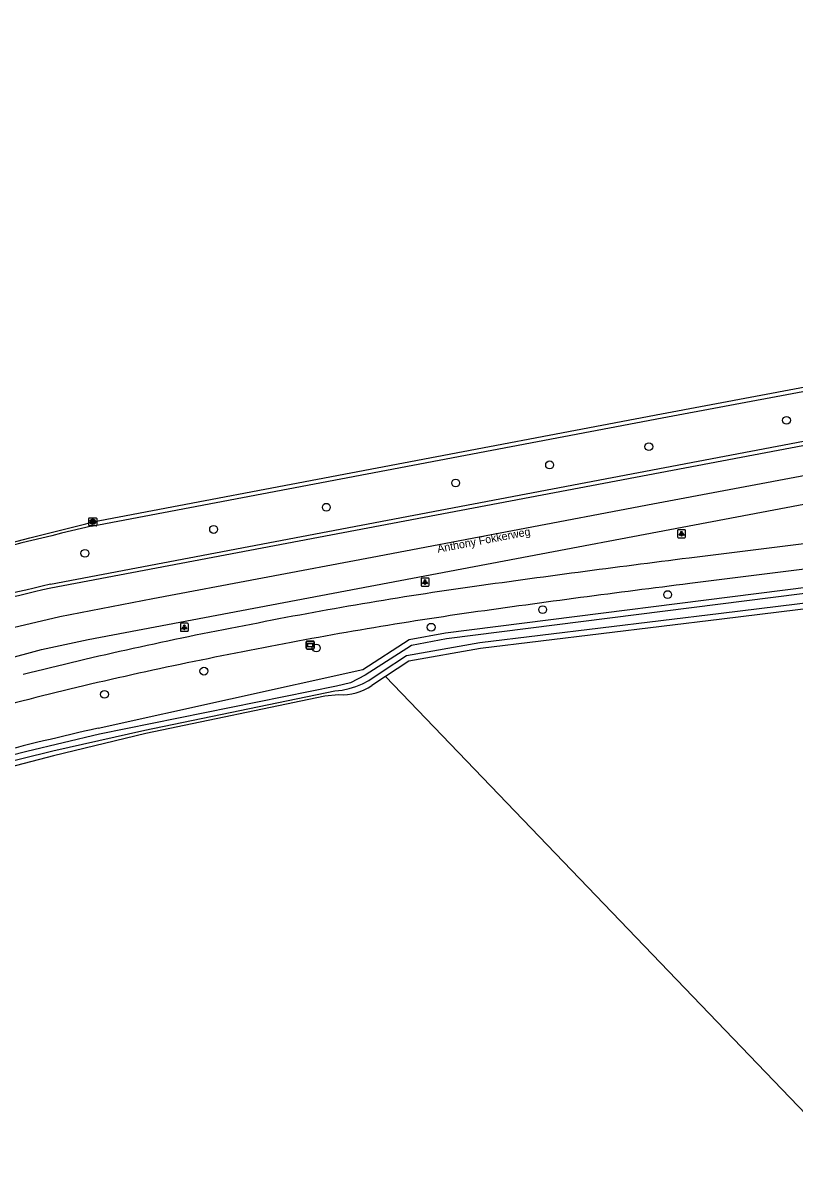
# Model space of a CAD drawing. Extents: x 157154 to 159278, y 385000 to 386650.
# Drawn here: x 157669 to 157765.4, y 386325.8 to 386470 of the extents above; entities that cross this region are included whole.
import ezdxf

# ---------------------------------------------------------------- set-up
doc = ezdxf.new("R2010")
doc.units = 0
for name, color, linetype in [('IMGEO_Berm_open', 7, 'Continuous'), ('IMGEO_Boom', 7, 'Continuous'), ('IMGEO_Bouwland', 7, 'Continuous'), ('IMGEO_Fietspad_open', 7, 'Continuous'), ('IMGEO_Groenvoorziening', 7, 'Continuous'), ('IMGEO_Kolk', 7, 'Continuous'), ('IMGEO_Lichtpunt', 7, 'Continuous'), ('IMGEO_Loofbos', 7, 'Continuous'), ('IMGEO_Openbare_ruimte_label', 7, 'Continuous'), ('IMGEO_Rijbaan_regionaal_gesloten', 7, 'Continuous'), ('IMGEO_Verklikker', 7, 'Continuous'), ('IMGEO_Waterloop', 7, 'Continuous')]:
    doc.layers.add(name, color=color, linetype=linetype)

msp = doc.modelspace()

# ---------------------------------------------------------------- linework, layer by layer
at = {"layer": 'IMGEO_Berm_open'}
for points in [[(157677.57, 386407.16), (157748.87, 386420.72), (157813.78, 386432.88)], [(157825.85, 386429.16), (157816.05, 386427.15), (157672.45, 386399.91)]]:
    msp.add_lwpolyline(points, dxfattribs=at)
for centre, radius, start, end in [((157790.4, 385918.61), 501.41, 103.0044, 107.6634), ((157771.77, 385969.6), 441.63, 102.9972, 107.3297)]:
    msp.add_arc(centre, radius, start, end, dxfattribs=at)
at = {"layer": 'IMGEO_Boom'}
for centre in [(157764.38, 386420.4), (157747.19, 386417.1), (157734.79, 386414.83), (157723.06, 386412.57), (157706.91, 386409.54), (157692.83, 386406.77), (157676.76, 386403.79), (157749.53, 386398.63), (157733.92, 386396.75), (157720, 386394.55), (157705.65, 386391.96), (157691.62, 386389.07), (157679.2, 386386.17)]:
    msp.add_circle(centre, 0.489, dxfattribs=at)
at = {"layer": 'IMGEO_Bouwland'}
for points in [[(157714.3, 386388.38), (157712.61, 386387.26)], [(157708.44, 386386.13), (157706.71, 386385.94), (157684.36, 386381.3), (157672.84, 386378.51), (157661.47, 386375.55)]]:
    msp.add_lwpolyline(points, dxfattribs=at)
msp.add_arc((157708.88, 386392.77), 6.65, 266.2635, 304.121, dxfattribs=at)
at = {"layer": 'IMGEO_Fietspad_open'}
for points in [[(157892.32, 386418.11), (157877, 386416.04), (157846.47, 386412.19), (157831.97, 386409.98), (157787.26, 386404.39), (157752.3, 386400)], [(157833.7, 386413.41), (157786.88, 386407.53), (157752.22, 386403.2)]]:
    msp.add_lwpolyline(points, dxfattribs=at)
for centre, radius, start, end in [((157993.4, 384480.42), 1937.84, 97.14941, 97.97507), ((157794.41, 385908.3), 496.16, 98.0956, 101.363), ((157954.91, 384768.71), 1643.83, 97.07995, 98.04006), ((157794.39, 385908.46), 492.83, 98.0942, 101.358), ((157786.26, 385923.76), 479.43, 100.7721, 104.1519), ((157781.31, 385945.65), 453.82, 100.6636, 104.2298), ((157811.65, 385852.76), 551.36, 104.9133, 107.8447)]:
    msp.add_arc(centre, radius, start, end, dxfattribs=at)
at = {"layer": 'IMGEO_Groenvoorziening'}
msp.add_lwpolyline([(157678.41, 386381.94), (157711.46, 386389.29), (157717.26, 386393.02), (157721.8, 386393.84), (157916.46, 386418.5)], dxfattribs=at)
msp.add_arc((157787.04, 385903.02), 491.09, 102.7805, 106.0498, dxfattribs=at)
at = {"layer": 'IMGEO_Kolk'}
for p, q in [((157677.23, 386407.29), (157677.23, 386408.14)), ((157677.31, 386408.22), (157678.16, 386408.22)), ((157677.72, 386408), (157677.75, 386408)), ((157678.24, 386408.14), (157678.24, 386407.29)), ((157678.16, 386407.22), (157677.31, 386407.22)), ((157677.74, 386407.44), (157677.72, 386407.44))]:
    msp.add_line(p, q, dxfattribs=at)
for points in [[(157677.23, 386407.29), (157677.23, 386408.14)], [(157677.31, 386408.22), (157678.16, 386408.22)], [(157678.24, 386408.14), (157678.24, 386407.29)], [(157678.16, 386407.22), (157677.31, 386407.22)], [(157677.55, 386407.92), (157677.68, 386407.92), (157677.68, 386407.77), (157677.81, 386407.92), (157677.97, 386407.92), (157677.83, 386407.77), (157677.98, 386407.52), (157677.83, 386407.52), (157677.74, 386407.68), (157677.68, 386407.61), (157677.68, 386407.52), (157677.55, 386407.52), (157677.55, 386407.92)]]:
    msp.add_lwpolyline(points, dxfattribs=at)
for centre, start, end in [((157677.31, 386408.14), 91.552, 178.448), ((157677.31, 386408.14), 91.552, 178.448), ((157678.16, 386408.14), 1.552, 88.448), ((157678.16, 386408.14), 1.552, 88.448), ((157677.31, 386407.29), 181.552, 268.448), ((157677.31, 386407.29), 181.552, 268.448), ((157678.16, 386407.29), 271.552, 358.448), ((157678.16, 386407.29), 271.552, 358.448)]:
    msp.add_arc(centre, 0.0765, start, end, dxfattribs=at)
for centre, major_axis, ratio, start_param, end_param in [((157677.72, 386407.72), (-0.387, 0.002), 0.722429, 4.712389, 7.853982), ((157677.75, 386407.72), (-0.39, 0.002), 0.717154, 1.570796, 4.712389)]:
    msp.add_ellipse(centre, major_axis=major_axis, ratio=ratio, start_param=start_param, end_param=end_param, dxfattribs=at)
at = {"layer": 'IMGEO_Lichtpunt'}
for p, q in [((157750.77, 386406.64), (157750.77, 386405.83)), ((157750.77, 386406.64), (157750.77, 386405.83)), ((157751.67, 386406.73), (157750.86, 386406.73)), ((157751.67, 386406.73), (157750.86, 386406.73)), ((157751.77, 386405.83), (157751.77, 386406.64)), ((157751.77, 386405.83), (157751.77, 386406.64)), ((157750.86, 386405.73), (157751.67, 386405.73)), ((157750.86, 386405.73), (157751.67, 386405.73)), ((157718.74, 386400.6), (157718.74, 386399.79)), ((157718.74, 386400.6), (157718.74, 386399.79)), ((157719.65, 386400.69), (157718.84, 386400.69)), ((157719.65, 386400.69), (157718.84, 386400.69)), ((157718.84, 386399.7), (157719.65, 386399.7)), ((157718.84, 386399.7), (157719.65, 386399.7)), ((157719.74, 386399.79), (157719.74, 386400.6)), ((157719.74, 386399.79), (157719.74, 386400.6)), ((157689.58, 386395.05), (157688.78, 386395.05)), ((157689.58, 386395.05), (157688.78, 386395.05)), ((157688.68, 386394.96), (157688.68, 386394.15)), ((157688.68, 386394.96), (157688.68, 386394.15)), ((157688.78, 386394.05), (157689.58, 386394.05)), ((157688.78, 386394.05), (157689.58, 386394.05)), ((157689.68, 386394.15), (157689.68, 386394.96)), ((157689.68, 386394.15), (157689.68, 386394.96))]:
    msp.add_line(p, q, dxfattribs=at)
for points in [[(157751.14, 386406.3), (157751.18, 386406.27), (157751, 386406.01), (157750.96, 386406.04), (157751.14, 386406.3)], [(157751.25, 386406.25), (157751.29, 386406.25), (157751.29, 386405.93), (157751.25, 386405.93), (157751.25, 386406.25)], [(157751.36, 386406.27), (157751.39, 386406.3), (157751.58, 386406.04), (157751.54, 386406.01), (157751.36, 386406.27)], [(157719.12, 386400.26), (157719.16, 386400.23), (157718.97, 386399.97), (157718.93, 386400), (157719.12, 386400.26)], [(157719.22, 386400.21), (157719.27, 386400.21), (157719.27, 386399.89), (157719.22, 386399.89), (157719.22, 386400.21)], [(157719.33, 386400.23), (157719.37, 386400.26), (157719.55, 386400), (157719.52, 386399.97), (157719.33, 386400.23)], [(157689.06, 386394.62), (157689.1, 386394.59), (157688.91, 386394.33), (157688.87, 386394.36), (157689.06, 386394.62)], [(157689.16, 386394.57), (157689.21, 386394.57), (157689.21, 386394.25), (157689.16, 386394.25), (157689.16, 386394.57)], [(157689.27, 386394.59), (157689.31, 386394.62), (157689.49, 386394.36), (157689.46, 386394.33), (157689.27, 386394.59)]]:
    msp.add_lwpolyline(points, dxfattribs=at)
for centre in [(157751.27, 386406.43), (157719.24, 386400.4), (157689.18, 386394.75)]:
    msp.add_circle(centre, 0.0994, dxfattribs=at)
for centre, start, end in [((157750.86, 386406.64), 90, 180), ((157750.86, 386406.64), 90, 180), ((157751.67, 386406.64), 0, 90), ((157751.67, 386406.64), 0, 90), ((157750.86, 386405.83), 180, 270), ((157750.86, 386405.83), 180, 270), ((157751.67, 386405.83), 270, 0), ((157751.67, 386405.83), 270, 360), ((157718.84, 386400.6), 90, 180), ((157718.84, 386400.6), 90, 180), ((157718.84, 386399.79), 180, 270), ((157718.84, 386399.79), 180, 270), ((157719.65, 386400.6), 0, 90), ((157719.65, 386400.6), 0, 90), ((157719.65, 386399.79), 270, 0), ((157719.65, 386399.79), 270, 360), ((157688.78, 386394.96), 90, 180), ((157688.78, 386394.96), 90, 180), ((157689.58, 386394.96), 0, 90), ((157689.58, 386394.96), 0, 90), ((157688.78, 386394.15), 180, 270), ((157688.78, 386394.15), 180, 270), ((157689.58, 386394.15), 270, 0), ((157689.58, 386394.15), 270, 360)]:
    msp.add_arc(centre, 0.0946, start, end, dxfattribs=at)
at = {"layer": 'IMGEO_Loofbos'}
for points in [[(157850.89, 386407.19), (157756.29, 386395.57), (157726.18, 386391.88), (157717.22, 386390.31), (157714.3, 386388.38)], [(157714.3, 386388.38), (157801.18, 386297.94)]]:
    msp.add_lwpolyline(points, dxfattribs=at)
at = {"layer": 'IMGEO_Rijbaan_regionaal_gesloten'}
for points in [[(157589.94, 386378.98), (157598.68, 386382.58), (157600.92, 386383.53), (157610.21, 386387.16), (157613.38, 386388.34), (157623.21, 386391.87), (157629.98, 386394.14), (157638.12, 386396.74), (157640.8, 386397.6), (157647.58, 386399.62), (157650.63, 386400.53), (157660.03, 386403.12), (157663.33, 386404.02), (157669.9, 386405.73), (157676.87, 386407.48), (157677.74, 386407.72), (157748.77, 386421.2), (157813.68, 386433.39), (157837.1, 386438.58), (157865.93, 386446.88), (157894.12, 386457.52), (157921.21, 386470.01)], [(157672.51, 386399.46), (157816.13, 386426.67), (157825.96, 386428.65), (157835.9, 386430.97)], [(157586.87, 386361.94), (157598.41, 386367.06), (157605.44, 386369.88), (157619.91, 386375.39), (157629.56, 386378.95), (157641.3, 386382.98), (157643.11, 386383.56), (157654.52, 386387.21), (157661.82, 386389.18), (157671.33, 386391.76), (157677.17, 386393.04), (157804.84, 386417.18)], [(157767.4, 386413.63), (157747.69, 386409.91), (157712.63, 386403.25), (157685.26, 386398.11), (157673.63, 386395.85), (157661.94, 386393.12), (157654.3, 386390.99), (157642.84, 386387.53), (157631.47, 386383.82), (157616.54, 386378.44), (157601.75, 386372.59), (157587.17, 386366.22)]]:
    msp.add_lwpolyline(points, dxfattribs=at)
msp.add_arc((157770.41, 385975.21), 435.39, 102.9944, 107.3754, dxfattribs=at)
at = {"layer": 'IMGEO_Verklikker'}
for p, q in [((157704.4, 386391.93), (157704.4, 386392.73)), ((157704.4, 386392.73), (157704.4, 386391.93)), ((157704.5, 386392.83), (157705.29, 386392.83)), ((157705.29, 386392.83), (157704.5, 386392.83)), ((157705.39, 386392.73), (157705.39, 386391.93)), ((157705.39, 386391.93), (157705.39, 386392.73)), ((157705.29, 386391.83), (157704.5, 386391.83)), ((157704.5, 386391.83), (157705.29, 386391.83))]:
    msp.add_line(p, q, dxfattribs=at)
for points in [[(157704.5, 386392.56), (157705.28, 386392.56), (157705.28, 386392.09), (157704.5, 386392.09), (157704.5, 386392.56)], [(157704.56, 386392.49), (157704.56, 386392.16), (157705.22, 386392.16), (157705.22, 386392.49), (157704.56, 386392.49)]]:
    msp.add_lwpolyline(points, dxfattribs=at)
for centre, start, end in [((157704.5, 386392.73), 90, 180), ((157704.5, 386392.73), 90, 180), ((157705.29, 386392.73), 0, 90), ((157705.29, 386392.73), 360, 90), ((157704.5, 386391.93), 180, 270), ((157704.5, 386391.93), 180, 270), ((157705.29, 386391.93), 270, 0), ((157705.29, 386391.93), 270, 0)]:
    msp.add_arc(centre, 0.1, start, end, dxfattribs=at)
at = {"layer": 'IMGEO_Waterloop'}
for points in [[(157915.68, 386417.63), (157721.92, 386393.09), (157717.54, 386392.29), (157711.76, 386388.58), (157709.91, 386387.6), (157708.19, 386387.21), (157678.58, 386381.2), (157669.5, 386379.05), (157660.47, 386376.73)], [(157661.28, 386376.29), (157672.74, 386379.11), (157684.26, 386381.68), (157707.99, 386386.59), (157708.88, 386386.7), (157709.75, 386386.89), (157710.6, 386387.16), (157711.42, 386387.5), (157712.21, 386387.91), (157713.88, 386389.01), (157716.93, 386391.03), (157726.07, 386392.63), (157756.2, 386396.32), (157850.8, 386407.94)]]:
    msp.add_lwpolyline(points, dxfattribs=at)

# ---------------------------------------------------------------- texts
at = {"layer": 'IMGEO_Openbare_ruimte_label'}
msp.add_text('Anthony Fokkerweg', height=1, rotation=10.7816, dxfattribs=at).set_placement((157720.85, 386403.85))

doc.saveas('drawing.dxf')
